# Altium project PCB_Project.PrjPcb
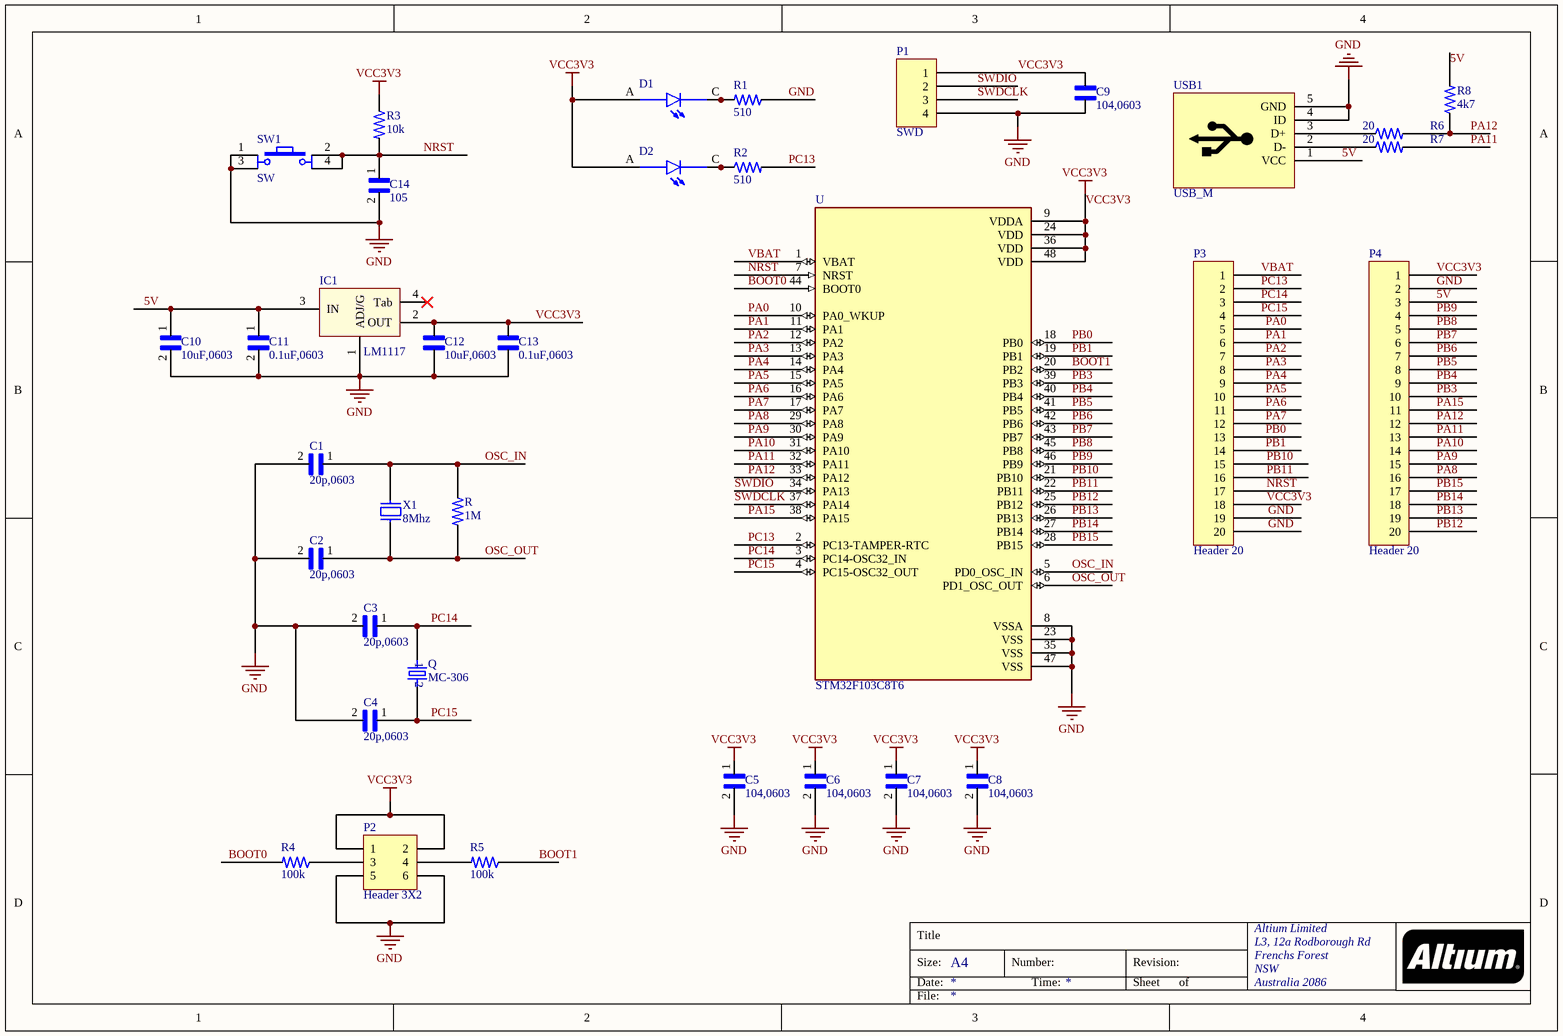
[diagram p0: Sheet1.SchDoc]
1 sheet, 35 parts. Net scope: global (net labels, ports and power ports of the same name join across sheets).
Board file: PCB1.PcbDoc

## Sheet Sheet1.SchDoc
size A4; Organization: Altium Limited; Address1: L3, 12a Rodborough Rd; Address2: Frenchs Forest; Address3: NSW; Address4: Australia 2086

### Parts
C1  20p,0603  [CAPC1608X90]
C2  20p,0603  [CAPC1608X90]
C3  20p,0603  [CAPC1608X90]
C4  20p,0603  [CAPC1608X90]
C5  104,0603  [CAPC1608X90]
C6  104,0603  [CAPC1608X90]
C7  104,0603  [CAPC1608X90]
C8  104,0603  [CAPC1608X90]
C9  104,0603  [CAPC1608X90]
C10  10uF,0603  [CAPC1608X90]
C11  0.1uF,0603  [CAPC1608X90]
C12  10uF,0603  [CAPC1608X90]
C13  0.1uF,0603  [CAPC1608X90]
C14  105  [CAPC1608X90]
D1  HSMS-C190  [LEDM1608X80]  (value not drawn)
D2  HSMS-C190  [LEDM1608X80]  (value not drawn)
IC1  LM1117  [SOT223-4N]
P1  SWD  [HDR1X4H]
P2  Header 3X2  [HDR2X3]
P3  Header 20  [HDR1X20]
P4  Header 20  [HDR1X20]
Q  MC-306  [XT 306]
R  1M  [RESC1608X50N]
R1  510  [RESC1608X50N]
R2  510  [RESC1608X50N]
R3  10k  [RESC1608X50N]
R4  100k  [RESC1608X50N]
R5  100k  [RESC1608X50N]
R6  20  [RESC1608X50N]
R7  20  [RESC1608X50N]
R8  4k7  [RESC1608X50N]
SW1  SW  [SW4]
U  STM32F103C8T6  [QFP50P900X900X160-48N]
USB1  USB_M  [USB_B_MINI_SMD]
X1  8Mhz  [XT2]

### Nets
GND: C1.2 C2.2 C3.2 C4.2 C5.2 C6.2 C7.2 C8.2 C9.2 C10.2 C11.2 C12.2 C13.2 C14.2 IC1.1(ADJ/G) P1.4 P2.5 P2.6 P3.19 P3.20 P4.2 R1.1 SW1.1 SW1.3 U.8(VSSA) U.23(VSS) U.35(VSS) U.47(VSS) USB1.4(ID) USB1.5(GND)
VCC3V3: C5.1 C6.1 C7.1 C8.1 C9.1 C12.1 C13.1 D1.A D2.A IC1.2(OUT) P1.1 P2.1 P2.2 P3.18 P4.1 R3.1 U.9(VDDA) U.24(VDD) U.36(VDD) U.48(VDD)
5V: C10.1 C11.1 IC1.3(IN) P4.3 R8.2 USB1.1(VCC)
BOOT0: R4.2 U.44(BOOT0)
BOOT1: R5.1 U.20(PB2)
NRST: C14.1 P3.17 R3.2 SW1.2 SW1.4 U.7(NRST)
OSC_IN: C1.1 R.1 U.5(PD0_OSC_IN) X1.2
OSC_OUT: C2.1 R.2 U.6(PD1_OSC_OUT) X1.1
PA0: P3.5 U.10(PA0_WKUP)
PA1: P3.6 U.11(PA1)
PA2: P3.7 U.12(PA2)
PA3: P3.8 U.13(PA3)
PA4: P3.9 U.14(PA4)
PA5: P3.10 U.15(PA5)
PA6: P3.11 U.16(PA6)
PA7: P3.12 U.17(PA7)
PA8: P4.16 U.29(PA8)
PA9: P4.15 U.30(PA9)
PA10: P4.14 U.31(PA10)
PA11: P4.13 R7.2 U.32(PA11)
PA12: P4.12 R6.2 R8.1 U.33(PA12)
PA15: P4.11 U.38(PA15)
PB0: P3.13 U.18(PB0)
PB1: P3.14 U.19(PB1)
PB3: P4.10 U.39(PB3)
PB4: P4.9 U.40(PB4)
PB5: P4.8 U.41(PB5)
PB6: P4.7 U.42(PB6)
PB7: P4.6 U.43(PB7)
PB8: P4.5 U.45(PB8)
PB9: P4.4 U.46(PB9)
PB10: P3.15 U.21(PB10)
PB11: P3.16 U.22(PB11)
PB12: P4.20 U.25(PB12)
PB13: P4.19 U.26(PB13)
PB14: P4.18 U.27(PB14)
PB15: P4.17 U.28(PB15)
PC13: P3.2 R2.2 U.2(PC13-TAMPER-RTC)
PC14: C3.1 P3.3 Q.1 U.3(PC14-OSC32_IN)
PC15: C4.1 P3.4 Q.4 U.4(PC15-OSC32_OUT)
SWDCLK: P1.3 U.37(PA14)
SWDIO: P1.2 U.34(PA13)
VBAT: P3.1 U.1(VBAT)
NetD1_C: D1.C R1.2
NetD2_C: D2.C R2.1
NetP2_3: P2.3 R4.1
NetP2_4: P2.4 R5.2
NetR6_1: R6.1 USB1.3(D+)
NetR7_1: R7.1 USB1.2(D-)

Not connected (* = marked no-connect by the designer): IC1 4(Tab)*

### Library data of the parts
C1-C14 = CC0603MRX7R9BB272: CAP CER 2700PF 50V X7R 0603
D1 D2 = HSMS-C190: Red 626nm LED Indication - Discrete 2.1V 0603 _1608 Metric_; MF: Broadcom Limited
IC1 = LM1117: 3v3; Value: LM317
P1 = Header 4H: Header, 4-Pin, Right Angle
P2 = Header 3X2: Header, 3-Pin, Dual row
P3 P4 = Header 20: Header, 20-Pin
Q = MC-306: 32.768kHz Â±100ppm Crystal 12.5pF 50 kOhms 4-SOJ, 5.50mm pitch; MF: Aigner
R R1-R8 = 2176051-4: RES 0.068 OHM 1% 1/8W 0603; Power_Rating: .125 W; MF: TE Connectivity; Resistance: .068
SW1 = SW4: Switch button 4 pin; Value: Button chip 4 pin
U = STM32F103C8T6: ARMÂ® CortexÂ®-M3 STM32F1 Microcontroller IC 32-Bit 72MHz 64KB _64K x 8_ FLASH; MF: STMicroelectronics
X1 = XT2: Crystal For all Crystal 2pin.; Value: 4Mhz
